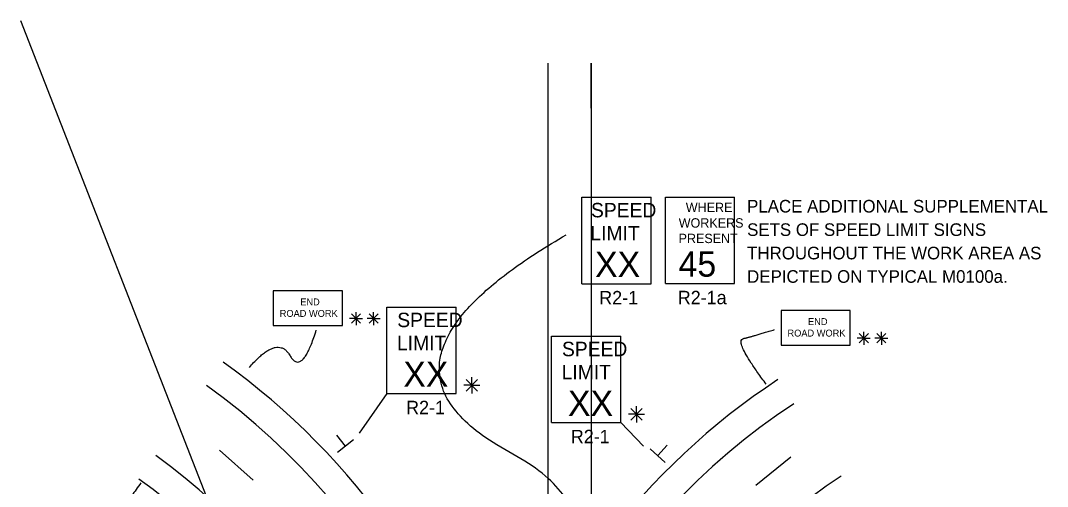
# Model space of a CAD drawing. Extents: x 16486 to 19506, y 5576 to 7023.
# Drawn here: x 16688 to 17258, y 6764 to 7023 of the extents above; entities that cross this region are included whole.
import ezdxf

# ---------------------------------------------------------------- set-up
doc = ezdxf.new("R2010")
doc.units = 0
for name, color, linetype in [('ALI_LEGAL_EX', 7, 'Continuous'), ('PAVT_EDGE_EX', 7, 'Continuous'), ('TRAFFIC_SIGNS_PR', 7, 'Continuous'), ('TYPICAL_TEXT_DIMEN_PR', 7, 'Continuous')]:
    doc.layers.add(name, color=color, linetype=linetype)

msp = doc.modelspace()

# ---------------------------------------------------------------- linework, layer by layer
at = {"layer": 'ALI_LEGAL_EX'}
for p, q in [((16687.64, 7022.55), (16909.67, 6454.18)), ((16980.24, 6998.86), (16980.24, 6180.72)), ((17004.24, 6998.86), (17004.24, 6180.72)), ((16980.24, 6946.95), (16980.24, 6083.04)), ((17004.24, 6946.95), (17004.24, 6083.04))]:
    msp.add_line(p, q, dxfattribs=at)
for points in [[(17004.24, 6973.86), (17004.24, 6998.86)], [(16816.64, 6767.46), (16797.97, 6784.09)], [(17095.66, 6764.69), (17115.12, 6780.39)]]:
    msp.add_lwpolyline(points, dxfattribs=at)
at = {"layer": 'PAVT_EDGE_EX'}
for centre, radius, start, end in [((16563.96, 6505.27), 404, 15.917, 54.2283), ((17315.96, 6505.27), 380, 123.1879, 163.0483), ((16563.96, 6505.27), 388, 0, 54.2283), ((17315.96, 6505.27), 364, 123.1879, 180), ((16563.96, 6505.27), 340, 0, 54.2283), ((16563.96, 6505.27), 324, 0, 54.2283), ((17315.96, 6505.27), 316, 123.1879, 180)]:
    msp.add_arc(centre, radius, start, end, dxfattribs=at)
at = {"layer": 'TRAFFIC_SIGNS_PR'}
for p, q in [((16999.16, 6924.48), (17037.56, 6924.48)), ((16999.16, 6876.48), (16999.16, 6924.48)), ((17037.56, 6876.48), (17037.56, 6924.48)), ((17045.5, 6924.57), (17083.9, 6924.57)), ((17045.5, 6876.57), (17045.5, 6924.57)), ((17083.9, 6876.57), (17083.9, 6924.57)), ((16999.16, 6876.48), (17037.56, 6876.48)), ((17045.5, 6876.57), (17083.9, 6876.57)), ((16890.93, 6863.54), (16929.33, 6863.54)), ((16890.93, 6815.54), (16890.93, 6863.54)), ((16929.33, 6815.54), (16929.33, 6863.54)), ((16982.31, 6847.43), (17020.71, 6847.43)), ((16982.31, 6799.43), (16982.31, 6847.43)), ((17020.71, 6799.43), (17020.71, 6847.43)), ((16890.93, 6815.54), (16929.33, 6815.54)), ((16982.31, 6799.43), (17020.71, 6799.43))]:
    msp.add_line(p, q, dxfattribs=at)
for points in [[(16827.86, 6853.37), (16866.26, 6853.37), (16866.26, 6872.57), (16827.86, 6872.57)], [(17109.64, 6842.45), (17148.04, 6842.45), (17148.04, 6861.65), (17109.64, 6861.65)]]:
    msp.add_lwpolyline(points, close=True, dxfattribs=at)
at = {"layer": 'TYPICAL_TEXT_DIMEN_PR'}
for p, q in [((16873.81, 6857.19), (16870.19, 6857.19)), ((16871.26, 6859.75), (16876.36, 6854.64)), ((16876.36, 6859.75), (16871.26, 6854.64)), ((16873.81, 6857.19), (16873.81, 6860.76)), ((16873.81, 6857.19), (16876.36, 6857.19)), ((16873.81, 6857.19), (16877.39, 6857.19)), ((16873.81, 6857.19), (16873.81, 6853.59)), ((16883.56, 6857.19), (16879.93, 6857.19)), ((16881.01, 6859.75), (16886.11, 6854.64)), ((16886.11, 6859.75), (16881.01, 6854.64)), ((16883.56, 6857.19), (16883.56, 6860.76)), ((16883.56, 6857.19), (16886.11, 6857.19)), ((16883.56, 6857.19), (16887.14, 6857.19)), ((16883.56, 6857.19), (16883.56, 6853.59)), ((17155.59, 6846.27), (17155.59, 6849.84)), ((17165.33, 6846.27), (17165.33, 6849.84)), ((17155.59, 6846.27), (17151.96, 6846.27)), ((17153.04, 6848.82), (17158.14, 6843.72)), ((17158.14, 6848.82), (17153.04, 6843.72)), ((17155.59, 6846.27), (17158.14, 6846.27)), ((17155.59, 6846.27), (17159.17, 6846.27)), ((17155.59, 6846.27), (17155.59, 6842.67)), ((17165.33, 6846.27), (17161.71, 6846.27)), ((17162.78, 6848.82), (17167.88, 6843.72)), ((17167.88, 6848.82), (17162.78, 6843.72)), ((17165.33, 6846.27), (17167.88, 6846.27)), ((17165.33, 6846.27), (17168.91, 6846.27)), ((17165.33, 6846.27), (17165.33, 6842.67)), ((16934.93, 6823.35), (16941.3, 6816.97)), ((16941.3, 6823.35), (16934.93, 6816.97)), ((16938.11, 6820.16), (16938.11, 6824.61)), ((16938.11, 6820.16), (16933.58, 6820.16)), ((16938.11, 6820.16), (16941.3, 6820.16)), ((16938.11, 6820.16), (16942.59, 6820.16)), ((16938.11, 6820.16), (16938.11, 6815.66)), ((16890.93, 6815.54), (16875.5, 6793.59)), ((17026.31, 6807.23), (17032.68, 6800.86)), ((17032.68, 6807.23), (17026.31, 6800.86)), ((17029.5, 6804.05), (17029.5, 6808.5)), ((17033.26, 6786.42), (17020.71, 6799.43)), ((17029.5, 6804.05), (17024.96, 6804.05)), ((17029.5, 6804.05), (17032.68, 6804.05)), ((17029.5, 6804.05), (17033.97, 6804.05)), ((17029.5, 6804.05), (17029.5, 6799.55)), ((16868, 6786.32), (16863.13, 6792.39)), ((16872.38, 6789.84), (16863.61, 6782.8)), ((17045.34, 6777.31), (17037.1, 6784.96)), ((17041.22, 6781.13), (17046.52, 6786.84))]:
    msp.add_line(p, q, dxfattribs=at)
for points in [[(16919.56, 6634.43), (17052.11, 6732.96), (16867.22, 6832.32), (16990.41, 6903.66)], [(16814.61, 6830.09), (16830.36, 6848.44), (16843.85, 6824.96), (16851.78, 6850.82)], [(17101.42, 6820.72), (17083.47, 6844.8), (17093.71, 6847.24), (17105.95, 6851.05)], [(16754.42, 6766.08), (16740.6, 6745.78), (16743.35, 6762.56), (16728.41, 6750.64)]]:
    msp.add_open_spline(points, degree=2, dxfattribs=at)

# ---------------------------------------------------------------- texts
at = {"layer": 'TRAFFIC_SIGNS_PR'}
for s, height, p in [('SPEED', 8, (17004.19, 6913.34)), ('WHERE', 5.2, (17056.81, 6916.25)), ('PLACE ADDITIONAL SUPPLEMENTAL', 7, (17090.83, 6916.02)), ('WORKERS', 5.2, (17052.88, 6907.65)), ('LIMIT', 8, (17003.86, 6900.54)), ('SETS OF SPEED LIMIT SIGNS', 7, (17090.83, 6903.02)), ('PRESENT', 5.2, (17052.81, 6899.05)), ('THROUGHOUT THE WORK AREA AS', 7, (17090.83, 6890.02)), ('XX', 14.031, (17006.46, 6880.24)), ('45', 14.031, (17052.8, 6880.42)), ('DEPICTED ON TYPICAL M0100a.', 7, (17090.83, 6877.02)), ('R2-1', 7.44, (17008.77, 6865.04)), ('R2-1a', 7.44, (17052.35, 6865.13)), ('END', 3.831, (16842.86, 6864.5)), ('ROAD WORK', 3.831, (16831.47, 6858.12)), ('SPEED', 8, (16896.69, 6852.41)), ('END', 3.831, (17124.64, 6853.58)), ('ROAD WORK', 3.831, (17113.24, 6847.2)), ('LIMIT', 8, (16896.53, 6839.61)), ('SPEED', 8, (16988.08, 6836.29)), ('XX', 14.031, (16900.04, 6819.3)), ('LIMIT', 8, (16987.92, 6823.49)), ('XX', 14.031, (16991.42, 6803.19)), ('R2-1', 7.44, (16901.6, 6804.1)), ('R2-1', 7.44, (16992.99, 6787.99))]:
    msp.add_text(s, height=height, dxfattribs=at).set_placement(p)

doc.saveas('drawing.dxf')
